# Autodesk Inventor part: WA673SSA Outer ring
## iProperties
Category: PARTsolutions
Created: 2011-07
Part Number: WA673SSA Outer ring
Catalog Web Link: www.cadenas.de
Description: Six types or - Metric system sizes
Document SubType Name: Modeling
Designer: PARTsolutions
Density: 1 g/cm^3
NB: WA673SSA Outer ring
NN: Six types or
NT: Metric system sizes
NBSYN: $ORDER. Outer ring
LINA: WA673SSA Outer ring
SD: 3.0
D: 6
B: 2.0
R: 0.08
ORDER: WA673SSA
CR: 242
COR: 94
CRF: 25
CORF: 9,5
LSG: 60 000
LSO: 71 000
MASS: 0.20
D1: 7.2
D2: 7.2
C1: 0.6
C2: 0.6
ORDER1: 673
WSS: WA673SSA
WDS: SSA
UTWF: FL673
FORSS: FLWA673SA
FORDS: SSA
DA1: 3,6
DA2: 4,1
DA: 5,4
RAS: 0,08
MASS1: 0.26
B1: 2.5
VERS: 3
X: 1.500
N: 9
O: 14.130
RB: 0.444
KT: DUMMY
SUPPLIER: NTN
ARTICLENO: WA673SSA Outer ring
BOMINFO: WA673SSA Outer ring
CREATOR: CADENAS GmbH
PSOL_IDENT_0: {\\10.0.0.251\ps_data\23d-libs\ntn\ball_roller_bearings\miniature_extra_small_bb\metric_system_sizes
PSOL_IDENT_1: \mss_or.prj},189 {VTYP=3D},{NB=WA673SSA Outer ring},{LINA=WA673SSA Outer ring},{NN=Six types or},{DA
PSOL_IDENT_2: TE=11.12.2007 08:48:24},{GEOMDATE=02.04.2007 00:00:00},{VERSION=},{LINEID=12590},{LINESUBID=-1},{WBV
PSOL_IDENT_3: AR=}  {NB=WA673SSA Outer ring},{LINA=WA673SSA Outer ring},{KT=DUMMY},{IDNR=},{SD=3.0},{D=6},{B=2.0},
PSOL_IDENT_4: {R=0.08},{ORDER=WA673SSA},{CR=242},{COR=94},{CRF=25},{CORF=9,5},{LSG=60 000},{LSO=71 000},{MASS=0.20
PSOL_IDENT_5: },{D1=7.2},{D2=7.2},{C1=0.6},{C2=0.6},{ORDER1=673},{WSS=WA673SSA},{WDS=SSA},{UTWF=FL673},{FORSS=FLWA
PSOL_IDENT_6: 673SA},{FORDS=SSA},{DA1=3,6},{DA2=4,1},{DA=5,4},{RAS=0,08},{MASS1=0.26},{B1=2.5},{VERS=3},{X=1.5},{N
PSOL_IDENT_7: =9},{O=14.13},{RB=0.444}
Title: WA673SSA Outer ring
Author: Cadenas PARTsolutions
Comments: Metric system sizes
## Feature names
1. Revolution1
